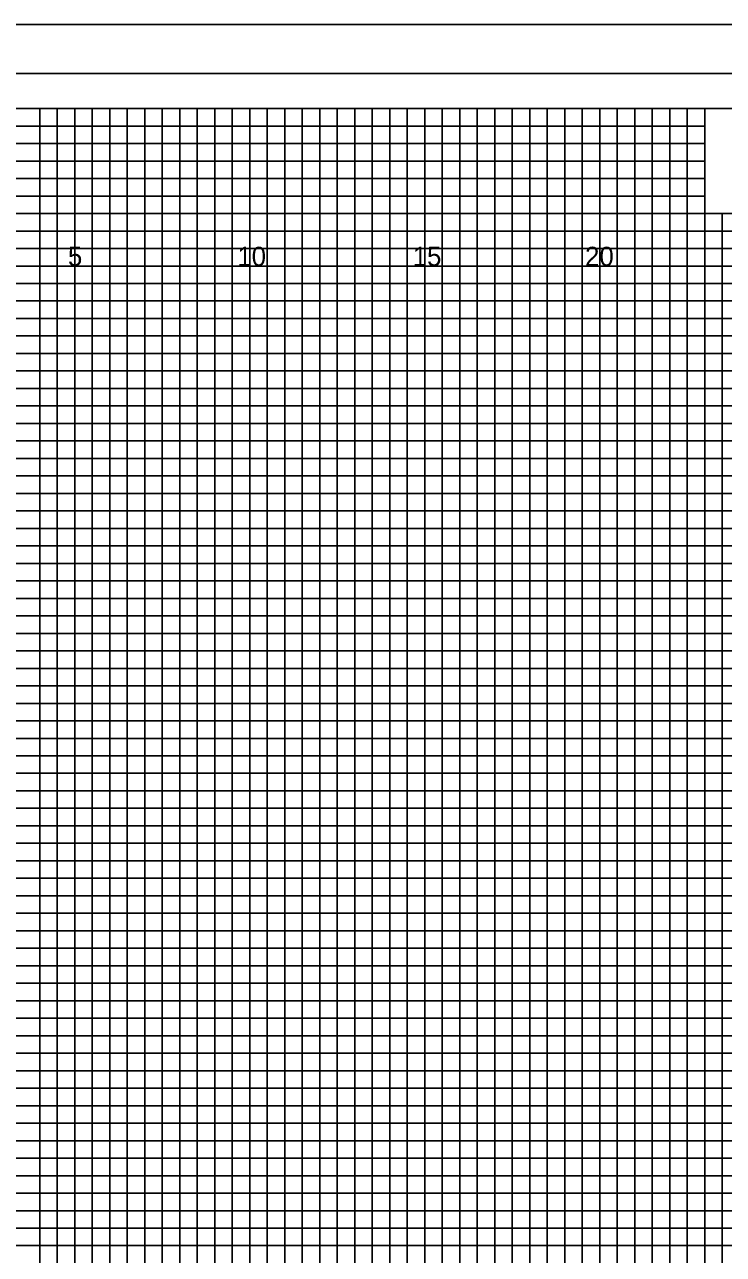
# Model space of a CAD drawing. Extents: x -4 to 103, y -2 to 280.
# Drawn here: x 54.82 to 74.78, y 103.08 to 138.22 of the extents above; entities that cross this region are included whole.
import ezdxf

# ---------------------------------------------------------------- set-up
doc = ezdxf.new("R2010")
doc.units = 0
for name, color, linetype in [('Exist XS Center Line Elevation Label', 7, 'Continuous'), ('Old_Level_63', 7, 'Continuous'), ('Prop XS Dump Level', 7, 'Continuous'), ('Prop XS Pvmt Edge Slope', 7, 'Continuous'), ('Prop XS SE Text', 7, 'Continuous'), ('Sheet Cutting Line CELL', 7, 'Continuous'), ('Sheet Plot Border Inside CELL', 7, 'Continuous'), ('Sheet Plot Border Outside CELL', 7, 'Continuous')]:
    doc.layers.add(name, color=color, linetype=linetype)

msp = doc.modelspace()

# ---------------------------------------------------------------- linework, layer by layer
at = {"layer": 'Exist XS Center Line Elevation Label'}
for points in [[(56.25, 70.825), (56.25, 135.825), (58.75, 135.825), (58.75, 70.825)], [(61.25, 70.825), (61.25, 135.825), (63.75, 135.825), (63.75, 70.825)], [(66.25, 70.825), (66.25, 135.825), (68.75, 135.825), (68.75, 70.825)], [(71.25, 70.825), (71.25, 135.825), (73.75, 135.825), (73.75, 70.825)], [(0, 133.325), (74.25, 133.325)], [(0, 128.325), (102.5, 128.325), (102.5, 130.825), (0, 130.825)], [(0, 123.325), (102.5, 123.325), (102.5, 125.825), (0, 125.825)], [(0, 118.325), (102.5, 118.325), (102.5, 120.825), (0, 120.825)], [(0, 113.325), (102.5, 113.325), (102.5, 115.825), (0, 115.825)], [(0, 108.325), (102.5, 108.325), (102.5, 110.825), (0, 110.825)], [(0, 103.325), (102.5, 103.325), (102.5, 105.825), (0, 105.825)]]:
    msp.add_lwpolyline(points, dxfattribs=at)
at = {"layer": 'Old_Level_63'}
for points in [[(102.5, 135.825), (0, 135.825), (0, 70.825), (102.5, 70.825)], [(83.75, 135.825), (74.25, 135.825), (74.25, 132.825), (83.75, 132.825)]]:
    msp.add_lwpolyline(points, close=True, dxfattribs=at)
at = {"layer": 'Prop XS Dump Level'}
for p, q in [((56.25, 70.825), (56.25, 135.825)), ((58.75, 70.825), (58.75, 135.825)), ((61.25, 70.825), (61.25, 135.825)), ((63.75, 70.825), (63.75, 135.825)), ((66.25, 70.825), (66.25, 135.825)), ((68.75, 70.825), (68.75, 135.825)), ((71.25, 70.825), (71.25, 135.825)), ((73.75, 70.825), (73.75, 135.825)), ((0, 133.325), (74.25, 133.325)), ((0, 130.825), (102.5, 130.825)), ((0, 128.325), (102.5, 128.325)), ((0, 125.825), (102.5, 125.825)), ((0, 123.325), (102.5, 123.325)), ((0, 120.825), (102.5, 120.825)), ((0, 118.325), (102.5, 118.325)), ((0, 115.825), (102.5, 115.825)), ((0, 113.325), (102.5, 113.325)), ((0, 110.825), (102.5, 110.825)), ((0, 108.325), (102.5, 108.325)), ((0, 105.825), (102.5, 105.825)), ((0, 103.325), (102.5, 103.325))]:
    msp.add_line(p, q, dxfattribs=at)
at = {"layer": 'Prop XS SE Text'}
for points in [[(55.25, 70.825), (55.25, 135.825), (55.75, 135.825), (55.75, 70.825)], [(56.75, 70.825), (56.75, 135.825), (57.25, 135.825), (57.25, 70.825)], [(57.75, 70.825), (57.75, 135.825), (58.25, 135.825), (58.25, 70.825)], [(59.25, 70.825), (59.25, 135.825), (59.75, 135.825), (59.75, 70.825)], [(60.25, 70.825), (60.25, 135.825), (60.75, 135.825), (60.75, 70.825)], [(61.75, 70.825), (61.75, 135.825), (62.25, 135.825), (62.25, 70.825)], [(62.75, 70.825), (62.75, 135.825), (63.25, 135.825), (63.25, 70.825)], [(64.25, 70.825), (64.25, 135.825), (64.75, 135.825), (64.75, 70.825)], [(65.25, 70.825), (65.25, 135.825), (65.75, 135.825), (65.75, 70.825)], [(66.75, 70.825), (66.75, 135.825), (67.25, 135.825), (67.25, 70.825)], [(67.75, 70.825), (67.75, 135.825), (68.25, 135.825), (68.25, 70.825)], [(69.25, 70.825), (69.25, 135.825)], [(69.25, 135.825), (69.75, 135.825), (69.75, 70.825)], [(70.25, 70.825), (70.25, 135.825), (70.75, 135.825), (70.75, 70.825)], [(71.75, 70.825), (71.75, 135.825), (72.25, 135.825), (72.25, 70.825)], [(72.75, 70.825), (72.75, 135.825), (73.25, 135.825), (73.25, 70.825)], [(0, 132.825), (0, 133.825), (74.25, 133.825), (74.25, 134.325), (0, 134.325), (0, 134.825), (74.25, 134.825), (74.25, 135.325), (0, 135.325)], [(0, 132.325), (102.5, 132.325), (102.5, 132.825), (0, 132.825)], [(74.25, 70.825), (74.25, 132.825), (74.75, 132.825), (74.75, 70.825)], [(0, 131.325), (102.5, 131.325), (102.5, 131.825), (0, 131.825)], [(0, 129.825), (102.5, 129.825), (102.5, 130.325), (0, 130.325)], [(0, 128.825), (102.5, 128.825), (102.5, 129.325), (0, 129.325)], [(0, 127.325), (102.5, 127.325), (102.5, 127.825), (0, 127.825)], [(0, 126.325), (102.5, 126.325), (102.5, 126.825), (0, 126.825)], [(0, 124.825), (102.5, 124.825), (102.5, 125.325), (0, 125.325)], [(0, 123.825), (102.5, 123.825), (102.5, 124.325), (0, 124.325)], [(0, 122.325), (102.5, 122.325), (102.5, 122.825), (0, 122.825)], [(0, 121.325), (102.5, 121.325), (102.5, 121.825), (0, 121.825)], [(0, 119.825), (102.5, 119.825), (102.5, 120.325), (0, 120.325)], [(0, 118.825), (102.5, 118.825), (102.5, 119.325), (0, 119.325)], [(0, 117.325), (102.5, 117.325), (102.5, 117.825), (0, 117.825)], [(0, 116.325), (102.5, 116.325), (102.5, 116.825), (0, 116.825)], [(0, 114.825), (102.5, 114.825), (102.5, 115.325), (0, 115.325)], [(0, 113.825), (102.5, 113.825), (102.5, 114.325), (0, 114.325)], [(0, 112.325), (102.5, 112.325), (102.5, 112.825), (0, 112.825)], [(0, 111.325), (102.5, 111.325), (102.5, 111.825), (0, 111.825)], [(0, 109.825), (102.5, 109.825), (102.5, 110.325), (0, 110.325)], [(0, 108.825), (102.5, 108.825), (102.5, 109.325), (0, 109.325)], [(0, 107.325), (102.5, 107.325), (102.5, 107.825), (0, 107.825)], [(0, 106.325), (102.5, 106.325), (102.5, 106.825), (0, 106.825)], [(0, 104.825), (102.5, 104.825), (102.5, 105.325), (0, 105.325)], [(0, 103.825), (102.5, 103.825), (102.5, 104.325), (0, 104.325)]]:
    msp.add_lwpolyline(points, dxfattribs=at)
at = {"layer": 'Sheet Cutting Line CELL'}
msp.add_line((-3.5, 138.225), (103.4, 138.225), dxfattribs=at)
at = {"layer": 'Sheet Plot Border Inside CELL'}
msp.add_lwpolyline([(103, 136.825), (-2.8, 136.825), (-2.8, 69.825), (103, 69.825)], close=True, dxfattribs=at)
at = {"layer": 'Sheet Plot Border Outside CELL'}
msp.add_lwpolyline([(103.4, 138.225), (-3.5, 138.225), (-3.5, 68.4), (103.4, 68.4)], close=True, dxfattribs=at)

# ---------------------------------------------------------------- texts
at = {"layer": 'Prop XS Pvmt Edge Slope'}
for s, p in [('5', (56.057, 131.325)), ('10', (60.897, 131.325)), ('15', (65.906, 131.325)), ('20', (70.831, 131.325))]:
    msp.add_text(s, height=0.55, dxfattribs=at).set_placement(p)

doc.saveas('drawing.dxf')
